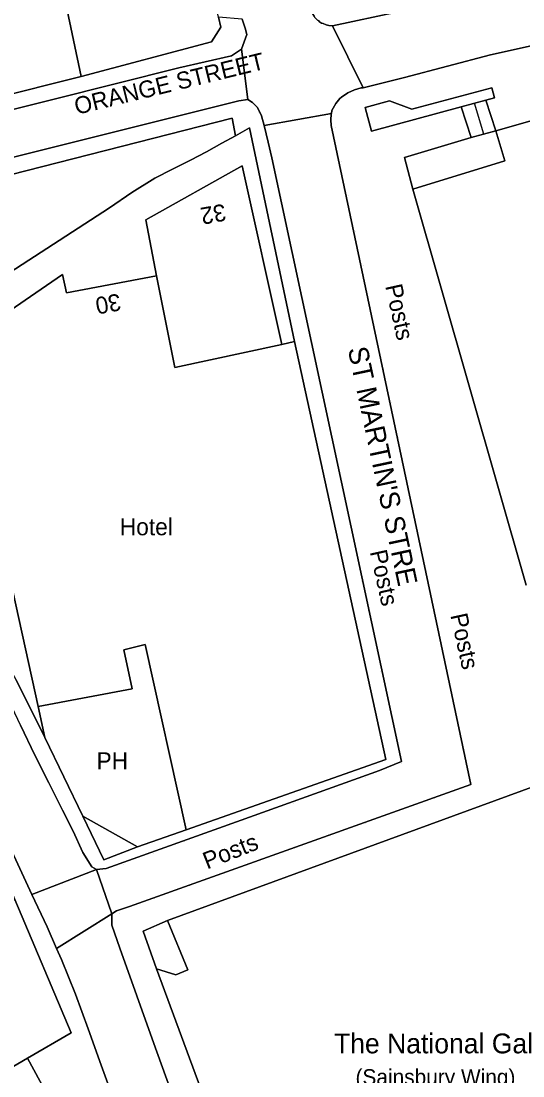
# Model space of a CAD drawing. Extents: x 529240 to 530363, y 179600 to 180767.
# Drawn here: x 529848.2 to 529892.4, y 180519 to 180612.1 of the extents above; entities that cross this region are included whole.
import ezdxf

# ---------------------------------------------------------------- set-up
doc = ezdxf.new("R2010")
doc.units = 0
for name, color, linetype in [('Building', 7, 'Continuous'), ('General surface', 7, 'Continuous'), ('Road Or Track', 7, 'Continuous'), ('Roadside', 7, 'Continuous'), ('Structure', 7, 'Continuous'), ('Unclassified', 7, 'Continuous')]:
    doc.layers.add(name, color=color, linetype=linetype)

msp = doc.modelspace()

# ---------------------------------------------------------------- linework, layer by layer
at = {"layer": 'Building'}
for points in [[(529818.119, 180614), (529820.25, 180609.6), (529826.15, 180611.35), (529828.25, 180611.95), (529829, 180609.45), (529827.9, 180609.15), (529829.75, 180601.3), (529853.45, 180607.25), (529852.1, 180613.65), (529852.019, 180614)], [(529882.7, 180597.3), (529890.8, 180599.8), (529890, 180602.45), (529887.85, 180601.85), (529881.95, 180600.1)], [(529860.1, 180589.65), (529861.7, 180581.55), (529871.15, 180583.6), (529867.65, 180599.35), (529859.15, 180594.6)], [(529860.1, 180589.65), (529852.15, 180588.15), (529851.8, 180589.75), (529838.3, 180580.5), (529840.55, 180576.35), (529841.8, 180576.65), (529842, 180575.7), (529844.25, 180576.15), (529849.65, 180551.65), (529857.95, 180553.2), (529857.2, 180556.65), (529859.1, 180557.1), (529862.7, 180540.75), (529880.3, 180546.95), (529872.25, 180583.85), (529871.15, 180583.6), (529861.7, 180581.55)], [(529853.6, 180541.95), (529858.4, 180539.25), (529862.7, 180540.75), (529859.1, 180557.1), (529857.2, 180556.65), (529857.95, 180553.2), (529849.65, 180551.65), (529850.25, 180548.9)], [(529858.4, 180539.25), (529853.6, 180541.95), (529855.45, 180538.1)], [(529841.45, 180531.1), (529838.15, 180529.3), (529836.4, 180528.3), (529842.1, 180518.55), (529842.85, 180517.2), (529848.7, 180520.6), (529852.55, 180522.85), (529847.6, 180534.6)], [(529841.25, 180506.1), (529853, 180512.7), (529848.7, 180520.6), (529842.85, 180517.2), (529836.9, 180513.75)]]:
    msp.add_lwpolyline(points, close=True, dxfattribs=at)
for points in [[(529853.45, 180607.25), (529852.1, 180613.65)], [(529915.25, 180609.65), (529890, 180602.45), (529890.8, 180599.8), (529882.7, 180597.3), (529892.7, 180562.35)], [(529890, 180602.45), (529915.25, 180609.65)], [(529829.75, 180601.3), (529853.45, 180607.25)], [(529838.3, 180580.5), (529851.8, 180589.75), (529852.15, 180588.15), (529860.1, 180589.65), (529859.15, 180594.6), (529867.65, 180599.35), (529871.15, 180583.6), (529872.25, 180583.85), (529868.3, 180602.7), (529867.05, 180602), (529865.85, 180601.35), (529864.5, 180600.6), (529863.1, 180599.85), (529861.5, 180599.05), (529859.95, 180598.25), (529857.9, 180597), (529855.95, 180595.65), (529833.9, 180581.35)], [(529867.05, 180602), (529868.3, 180602.7), (529872.25, 180583.85)], [(529833.9, 180581.35), (529855.95, 180595.65), (529857.9, 180597), (529859.95, 180598.25), (529861.5, 180599.05), (529863.1, 180599.85), (529864.5, 180600.6), (529865.85, 180601.35), (529867.05, 180602)], [(529882.7, 180597.3), (529881.95, 180600.1), (529887.85, 180601.85)], [(529882.7, 180597.3), (529890.8, 180599.8), (529890, 180602.45)], [(529887.85, 180601.85), (529890, 180602.45)], [(529860.1, 180589.65), (529859.15, 180594.6), (529867.65, 180599.35), (529871.15, 180583.6)], [(529892.7, 180562.35), (529882.7, 180597.3)], [(529849.65, 180551.65), (529844.25, 180576.15), (529842, 180575.7), (529841.8, 180576.65), (529840.55, 180576.35), (529838.3, 180580.5), (529851.8, 180589.75), (529852.15, 180588.15), (529860.1, 180589.65)], [(529871.15, 180583.6), (529861.7, 180581.55), (529860.1, 180589.65)], [(529872.25, 180583.85), (529880.3, 180546.95), (529862.7, 180540.75)], [(529871.15, 180583.6), (529872.25, 180583.85)], [(529850.25, 180548.9), (529847.7, 180554), (529846.8, 180555.65), (529846.4, 180556.45), (529846.05, 180557.25), (529845.75, 180558.05), (529845.5, 180558.9), (529845.25, 180559.85), (529845.05, 180560.9), (529843.75, 180566.65), (529841.7, 180575.05), (529837.65, 180573.95), (529833.9, 180581.35)], [(529847.7, 180554), (529850.25, 180548.9), (529849.65, 180551.65), (529844.25, 180576.15)], [(529862.7, 180540.75), (529859.1, 180557.1), (529857.2, 180556.65), (529857.95, 180553.2), (529849.65, 180551.65)], [(529850.25, 180548.9), (529849.65, 180551.65)], [(529853.6, 180541.95), (529850.25, 180548.9)], [(529896.8, 180545.85), (529861.05, 180532.75), (529862.85, 180528.4), (529861.8, 180527.95), (529860.1, 180528.5), (529870.6, 180500), (529871.7, 180496.95), (529883.95, 180475.65), (529885.2, 180476.45), (529887.05, 180473.25), (529895, 180477.75)], [(529897.15, 180544.85), (529896.8, 180545.85), (529861.05, 180532.75)], [(529858.4, 180539.25), (529855.45, 180538.1), (529853.6, 180541.95)], [(529853.6, 180541.95), (529858.4, 180539.25)], [(529862.7, 180540.75), (529858.4, 180539.25)], [(529847.6, 180534.6), (529852.55, 180522.85), (529848.7, 180520.6)], [(529861.05, 180532.75), (529862.85, 180528.4), (529861.8, 180527.95), (529860.1, 180528.5)], [(529860.1, 180528.5), (529870.6, 180500), (529871.7, 180496.95), (529883.95, 180475.65), (529885.2, 180476.45), (529887.05, 180473.25), (529895, 180477.75)], [(529848.7, 180520.6), (529842.85, 180517.2)], [(529848.7, 180520.6), (529853, 180512.7)]]:
    msp.add_lwpolyline(points, dxfattribs=at)
at = {"layer": 'General surface'}
for points in [[(529853.669, 180614), (529852.1, 180613.65), (529853.45, 180607.25), (529864.95, 180610.3), (529865.75, 180611.6), (529865.56, 180612.46), (529865.209, 180614)], [(529874.353, 180614), (529873.45, 180613.65), (529873.7, 180613.1), (529873.85, 180612.8), (529874, 180612.55), (529874.05, 180612.45), (529874.3, 180612.2), (529874.4, 180612.15), (529874.45, 180612.05), (529874.65, 180611.95), (529874.8, 180611.9), (529875.05, 180611.8), (529875.3, 180611.75), (529875.6, 180611.7), (529881.4, 180612.95), (529885.45, 180613.9), (529885.838, 180614), (529880.45, 180614), (529876.05, 180612.9), (529875.15, 180613.2), (529874.97, 180614)], [(529889.14, 180605.14), (529886.95, 180604.55), (529887.85, 180601.85), (529890, 180602.45)], [(529861.05, 180532.75), (529858.9, 180531.8), (529860.1, 180528.5), (529861.8, 180527.95), (529862.85, 180528.4)]]:
    msp.add_lwpolyline(points, close=True, dxfattribs=at)
for points in [[(529886.95, 180604.55), (529887.85, 180601.85)], [(529888.95, 180602.16), (529888.14, 180604.87)], [(529889.14, 180605.14), (529890, 180602.45)]]:
    msp.add_lwpolyline(points, dxfattribs=at)
at = {"layer": 'Road Or Track'}
for points in [[(529941.295, 180614), (529885.838, 180614), (529885.45, 180613.9), (529881.4, 180612.95), (529875.6, 180611.7), (529878.3, 180606.25), (529881.95, 180607.15), (529889.55, 180609.15), (529896.05, 180610.6)], [(529885.838, 180614), (529885.45, 180613.9), (529881.4, 180612.95), (529875.6, 180611.7)], [(529875.6, 180611.7), (529875.3, 180611.75), (529875.05, 180611.8), (529874.8, 180611.9), (529874.65, 180611.95), (529874.45, 180612.05), (529874.4, 180612.15), (529874.3, 180612.2), (529874.05, 180612.45), (529874, 180612.55), (529873.85, 180612.8), (529873.7, 180613.1), (529873.45, 180613.65)], [(529867.65, 180612.3), (529867.9, 180611.5), (529868.05, 180610.95), (529867.6, 180609.65), (529868.15, 180605.2), (529868.55, 180604.95), (529869, 180604.5), (529869.35, 180603.75), (529869.57, 180602.92), (529875.51, 180603.97), (529875.55, 180604.25), (529875.9, 180604.85), (529876.25, 180605.3), (529876.4, 180605.4), (529876.95, 180605.8), (529877.55, 180606.05), (529878.15, 180606.25), (529878.3, 180606.25), (529875.6, 180611.7), (529875.3, 180611.75), (529875.05, 180611.8), (529874.8, 180611.9), (529874.65, 180611.95), (529874.45, 180612.05), (529874.4, 180612.15)], [(529867.65, 180612.3), (529867.9, 180611.5), (529868.05, 180610.95), (529867.6, 180609.65)], [(529878.3, 180606.25), (529881.95, 180607.15), (529889.55, 180609.15), (529896.05, 180610.6), (529898.95, 180611.25), (529901.4, 180611.6), (529905.35, 180611.7), (529909.15, 180611.75), (529913.1, 180611.55), (529920.55, 180611.2)], [(529867.6, 180609.65), (529866.7, 180609.05), (529862.05, 180608), (529850.95, 180605.2), (529825.55, 180598.85), (529824.45, 180598.65), (529823.88, 180598.76)], [(529875.51, 180603.97), (529875.55, 180604.25), (529875.9, 180604.85), (529876.25, 180605.3), (529876.4, 180605.4), (529876.95, 180605.8), (529877.55, 180606.05), (529878.15, 180606.25), (529878.3, 180606.25)], [(529826.85, 180593.75), (529827.05, 180594.25), (529827.35, 180594.7), (529827.45, 180594.8), (529828.35, 180595.3), (529828.85, 180595.4), (529835.25, 180597.05), (529849.25, 180600.55), (529867.35, 180605.1), (529868.15, 180605.2)], [(529868.15, 180605.2), (529868.55, 180604.95), (529869, 180604.5), (529869.35, 180603.75), (529869.57, 180602.92)], [(529856.15, 180533.35), (529856.55, 180533.6), (529857.7, 180534), (529887.8, 180544.75), (529875.5, 180602.9), (529875.45, 180603.4), (529875.5, 180603.9), (529875.51, 180603.97)], [(529869.57, 180602.92), (529869.95, 180601.45), (529870.25, 180600.05), (529881.7, 180546.8), (529879.75, 180546), (529867.55, 180541.6), (529855.65, 180537.35), (529854.8, 180537.25)], [(529822.76, 180590.88), (529824.3, 180590.75), (529831.5, 180575.85), (529835.7, 180567), (529839.9, 180558.2), (529841.55, 180554.4), (529841.8, 180552.8), (529842.4, 180550.25), (529843.3, 180548), (529845.75, 180542.25), (529849.1, 180535.05)], [(529854.8, 180537.25), (529854.4, 180537.5), (529853.6, 180538.75), (529852.75, 180540.65), (529851.8, 180542.5), (529850.6, 180544.9), (529849.35, 180547.35), (529848.1, 180550), (529846.85, 180552.6), (529845.85, 180554.45), (529844.85, 180555.95), (529844.25, 180557), (529843.6, 180557.9), (529843.4, 180558.6), (529843.5, 180559.9), (529843.85, 180563.7), (529840.55, 180570.8), (529838.95, 180572.05), (529836.5, 180573.5), (529835.85, 180574)], [(529845.75, 180542.25), (529849.1, 180535.05), (529854.8, 180537.25), (529854.4, 180537.5), (529853.6, 180538.75), (529852.75, 180540.65), (529851.8, 180542.5), (529850.6, 180544.9), (529849.35, 180547.35), (529848.1, 180550)], [(529849.1, 180535.05), (529850.45, 180532.2), (529851.27, 180530.29)], [(529867.75, 180500), (529859.85, 180521.9), (529856.85, 180530.3), (529856.15, 180532.35), (529856.15, 180533.35), (529851.27, 180530.29), (529851.7, 180529.3), (529852.95, 180526.25), (529854.05, 180523.2), (529855.2, 180520), (529856.35, 180516.85)], [(529882.81, 180474.27), (529880.73, 180477.69), (529870.14, 180496.05), (529867.75, 180500), (529859.85, 180521.9), (529856.85, 180530.3), (529856.15, 180532.35), (529856.15, 180533.35)], [(529851.27, 180530.29), (529851.7, 180529.3), (529852.95, 180526.25), (529854.05, 180523.2), (529855.2, 180520), (529856.35, 180516.85), (529862.4, 180500), (529863.4, 180497.4), (529863.95, 180495.6), (529864, 180495.35), (529864.1, 180495.05), (529864.2, 180494.7), (529864.25, 180494.35), (529864.25, 180493.45), (529864.2, 180493.2), (529864.15, 180492.9), (529863.95, 180492.5), (529863.85, 180492.25), (529863.55, 180491.85), (529863.45, 180491.7), (529863.25, 180491.5), (529862.55, 180491)]]:
    msp.add_lwpolyline(points, dxfattribs=at)
for points in [[(529823.88, 180598.76), (529826.85, 180593.75), (529827.05, 180594.25), (529827.35, 180594.7), (529827.45, 180594.8), (529828.35, 180595.3), (529828.85, 180595.4), (529835.25, 180597.05), (529849.25, 180600.55), (529867.35, 180605.1), (529868.15, 180605.2), (529867.6, 180609.65), (529866.7, 180609.05), (529862.05, 180608), (529850.95, 180605.2), (529825.55, 180598.85), (529824.45, 180598.65)], [(529856.15, 180533.35), (529856.55, 180533.6), (529857.7, 180534), (529887.8, 180544.75), (529875.5, 180602.9), (529875.45, 180603.4), (529875.5, 180603.9), (529875.51, 180603.97), (529869.57, 180602.92), (529869.95, 180601.45), (529870.25, 180600.05), (529881.7, 180546.8), (529879.75, 180546), (529867.55, 180541.6), (529855.65, 180537.35), (529854.8, 180537.25)], [(529856.15, 180533.35), (529854.8, 180537.25), (529849.1, 180535.05), (529850.45, 180532.2), (529851.27, 180530.29)]]:
    msp.add_lwpolyline(points, close=True, dxfattribs=at)
at = {"layer": 'Roadside'}
for p, q in [((529869.05, 180604.1), (529869.05, 180604.1)), ((529875.85, 180602.75), (529875.85, 180602.75)), ((529870.25, 180599.9), (529870.25, 180599.9)), ((529876.4, 180599.7), (529876.4, 180599.7)), ((529870.85, 180597.4), (529870.85, 180597.4)), ((529877.05, 180596.7), (529877.05, 180596.7)), ((529871.4, 180594.6), (529871.4, 180594.6)), ((529877.65, 180593.6), (529877.65, 180593.6)), ((529872, 180592.1), (529872, 180592.1)), ((529878.3, 180590.55), (529878.3, 180590.55)), ((529872.55, 180589.4), (529872.55, 180589.4)), ((529873.05, 180586.8), (529873.05, 180586.8)), ((529878.85, 180587.4), (529878.85, 180587.4)), ((529873.65, 180584.05), (529873.65, 180584.05)), ((529879.5, 180584.35), (529879.5, 180584.35)), ((529874.25, 180581.45), (529874.25, 180581.45)), ((529880.15, 180581.35), (529880.15, 180581.35)), ((529874.75, 180578.85), (529874.75, 180578.85)), ((529880.85, 180578.45), (529880.85, 180578.45)), ((529875.4, 180576.1), (529875.4, 180576.1)), ((529881.45, 180575.4), (529881.45, 180575.4)), ((529875.9, 180573.5), (529875.9, 180573.5)), ((529882, 180572.3), (529882, 180572.3)), ((529876.5, 180570.8), (529876.5, 180570.8)), ((529882.65, 180569.25), (529882.65, 180569.25)), ((529877.1, 180568.15), (529877.1, 180568.15)), ((529877.65, 180565.45), (529877.65, 180565.45)), ((529883.3, 180566.25), (529883.3, 180566.25)), ((529878.2, 180562.7), (529878.2, 180562.7)), ((529883.9, 180563.2), (529883.9, 180563.2)), ((529878.75, 180560.1), (529878.75, 180560.1)), ((529884.55, 180560.05), (529884.55, 180560.05)), ((529879.35, 180557.45), (529879.35, 180557.45)), ((529885.15, 180556.9), (529885.15, 180556.9)), ((529879.85, 180554.7), (529879.85, 180554.7)), ((529885.9, 180553.9), (529885.9, 180553.9)), ((529880.5, 180552.1), (529880.5, 180552.1)), ((529886.45, 180550.95), (529886.45, 180550.95)), ((529881.05, 180549.45), (529881.05, 180549.45)), ((529887.05, 180547.85), (529887.05, 180547.85)), ((529881.7, 180546.65), (529881.7, 180546.65)), ((529878.5, 180545.4), (529878.5, 180545.4)), ((529887.8, 180544.75), (529887.8, 180544.75)), ((529887.8, 180544.75), (529887.8, 180544.75)), ((529872.15, 180543.1), (529872.15, 180543.1)), ((529884.6, 180543.5), (529884.6, 180543.5)), ((529881.65, 180542.55), (529881.65, 180542.55)), ((529878.55, 180541.35), (529878.55, 180541.35)), ((529875.3, 180540.35), (529875.3, 180540.35)), ((529862.6, 180539.75), (529862.6, 180539.75)), ((529859.85, 180538.65), (529859.85, 180538.65)), ((529872.3, 180539.15), (529872.3, 180539.15)), ((529857.2, 180537.7), (529857.2, 180537.7)), ((529869.2, 180538.05), (529869.2, 180538.05)), ((529866.1, 180536.9), (529866.1, 180536.9)), ((529863, 180535.8), (529863, 180535.8)), ((529859.9, 180534.7), (529859.9, 180534.7)), ((529856.85, 180533.35), (529856.85, 180533.35))]:
    msp.add_line(p, q, dxfattribs=at)
for points in [[(529815.943, 180614), (529819.4, 180606.95), (529822.75, 180599.8), (529823.45, 180598.85), (529823.88, 180598.76), (529824.45, 180598.65), (529825.55, 180598.85), (529850.95, 180605.2), (529862.05, 180608), (529866.7, 180609.05), (529867.6, 180609.65), (529868.05, 180610.95), (529867.9, 180611.5), (529867.65, 180612.3), (529865.56, 180612.46), (529865.75, 180611.6), (529864.95, 180610.3), (529853.45, 180607.25), (529829.75, 180601.3), (529826.25, 180600.45), (529824.4, 180601.05), (529820.25, 180609.6), (529818.119, 180614)], [(529833.9, 180581.35), (529855.95, 180595.65), (529857.9, 180597), (529859.95, 180598.25), (529861.5, 180599.05), (529863.1, 180599.85), (529864.5, 180600.6), (529865.85, 180601.35), (529867.05, 180602), (529866.75, 180603.55), (529844.4, 180597.85), (529829.5, 180594.05), (529828.7, 180593.7), (529828.25, 180593.5), (529828.05, 180593.2), (529828, 180592.7), (529831.1, 180586.7)]]:
    msp.add_lwpolyline(points, close=True, dxfattribs=at)
for points in [[(529896.05, 180610.6), (529889.55, 180609.15), (529881.95, 180607.15), (529878.3, 180606.25), (529878.15, 180606.25), (529877.55, 180606.05), (529876.95, 180605.8), (529876.4, 180605.4), (529876.25, 180605.3), (529875.9, 180604.85), (529875.55, 180604.25), (529875.51, 180603.97), (529875.5, 180603.9), (529875.45, 180603.4), (529875.5, 180602.9), (529887.8, 180544.75), (529857.7, 180534), (529856.55, 180533.6), (529856.15, 180533.35), (529856.15, 180532.35), (529856.85, 180530.3), (529859.85, 180521.9), (529867.75, 180500)], [(529892.7, 180562.35), (529882.7, 180597.3), (529881.95, 180600.1), (529887.85, 180601.85), (529886.95, 180604.55), (529879.05, 180602.4), (529878.5, 180604.5), (529880.65, 180605.1), (529882.6, 180604.35), (529889.65, 180606.25), (529889.9, 180605.35), (529889.14, 180605.14), (529890, 180602.45), (529915.25, 180609.65)], [(529848.1, 180550), (529849.35, 180547.35), (529850.6, 180544.9), (529851.8, 180542.5), (529852.75, 180540.65), (529853.6, 180538.75), (529854.4, 180537.5), (529854.8, 180537.25), (529855.65, 180537.35), (529867.55, 180541.6), (529879.75, 180546), (529881.7, 180546.8), (529870.25, 180600.05), (529869.95, 180601.45), (529869.57, 180602.92), (529869.35, 180603.75), (529869, 180604.5), (529868.55, 180604.95), (529868.15, 180605.2), (529867.35, 180605.1), (529849.25, 180600.55), (529835.25, 180597.05)], [(529844.4, 180597.85), (529866.75, 180603.55), (529867.05, 180602), (529868.3, 180602.7), (529872.25, 180583.85), (529880.3, 180546.95), (529862.7, 180540.75), (529858.4, 180539.25), (529855.45, 180538.1), (529853.6, 180541.95), (529850.25, 180548.9), (529847.7, 180554)], [(529783.75, 180563.25), (529799.55, 180573.9), (529800.85, 180574.8), (529806, 180578.15), (529816, 180584.85), (529821.75, 180588.7), (529823.65, 180588.05), (529825.35, 180584.85), (529828.05, 180579.85), (529830.3, 180575.15), (529832.1, 180571.3), (529832.25, 180570.9), (529833.9, 180566.85), (529834.1, 180566.4), (529835.2, 180563.8), (529836.25, 180561.4), (529837.9, 180557.45), (529839.9, 180552.6), (529840.9, 180550.3), (529842.7, 180546), (529847.6, 180534.6), (529852.55, 180522.85), (529848.7, 180520.6), (529853, 180512.7)], [(529895, 180477.75), (529887.05, 180473.25), (529885.2, 180476.45), (529883.95, 180475.65), (529871.7, 180496.95), (529870.6, 180500), (529860.1, 180528.5), (529858.9, 180531.8), (529861.05, 180532.75), (529896.8, 180545.85)], [(529856.35, 180516.85), (529855.2, 180520), (529854.05, 180523.2), (529852.95, 180526.25), (529851.7, 180529.3), (529851.27, 180530.29), (529850.45, 180532.2), (529849.1, 180535.05), (529845.75, 180542.25)]]:
    msp.add_lwpolyline(points, dxfattribs=at)
at = {"layer": 'Structure'}
msp.add_lwpolyline([(529886.95, 180604.55), (529889.14, 180605.14), (529889.9, 180605.35), (529889.65, 180606.25), (529882.6, 180604.35), (529880.65, 180605.1), (529878.5, 180604.5), (529879.05, 180602.4)], close=True, dxfattribs=at)
at = {"layer": 'Unclassified'}
for points in [[(529853.45, 180607.25), (529864.95, 180610.3), (529865.75, 180611.6), (529865.56, 180612.46)], [(529875.6, 180611.7), (529878.3, 180606.25)], [(529867.6, 180609.65), (529868.15, 180605.2)], [(529879.05, 180602.4), (529878.5, 180604.5), (529880.65, 180605.1), (529882.6, 180604.35), (529889.65, 180606.25), (529889.9, 180605.35), (529889.14, 180605.14)], [(529886.95, 180604.55), (529879.05, 180602.4)], [(529889.14, 180605.14), (529886.95, 180604.55)], [(529844.4, 180597.85), (529866.75, 180603.55), (529867.05, 180602)], [(529875.51, 180603.97), (529869.57, 180602.92)], [(529849.1, 180535.05), (529854.8, 180537.25)], [(529854.8, 180537.25), (529856.15, 180533.35)], [(529856.15, 180533.35), (529851.27, 180530.29)], [(529861.05, 180532.75), (529858.9, 180531.8), (529860.1, 180528.5)]]:
    msp.add_lwpolyline(points, dxfattribs=at)

# ---------------------------------------------------------------- texts
at = {"layer": 'Road Or Track'}
for s, height, rotation, p in [('ORANGE STREET', 1.5, 13.7, (529853.05, 180603.85)), ("ST MARTIN'S STRE", 1.75, 282, (529876.95, 180583.2))]:
    msp.add_text(s, height=height, rotation=rotation, dxfattribs=at).set_placement(p)
at = {"layer": 'Roadside'}
for rotation, p in [(282.4, (529880.25, 180588.75)), (282.4, (529878.9, 180565.3)), (282.4, (529886, 180559.7)), (21.7, (529864.55, 180537.25))]:
    msp.add_text('Posts', height=1.5, rotation=rotation, dxfattribs=at).set_placement(p)
at = {"layer": 'Unclassified'}
for s, p in [('32', (529866.07, 180596.02)), ('30', (529856.8, 180588.1))]:
    msp.add_text(s, height=1.5, rotation=190.1, dxfattribs=at).set_placement(p)
for s, height, p in [('Hotel', 1.5, (529856.85, 180566.75)), ('PH', 1.5, (529854.8, 180546.1)), ('The National Gal', 1.75, (529875.74, 180521.03)), ('(Sainsbury Wing)', 1.375, (529877.64, 180518.26))]:
    msp.add_text(s, height=height, dxfattribs=at).set_placement(p)

doc.saveas('drawing.dxf')
